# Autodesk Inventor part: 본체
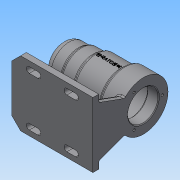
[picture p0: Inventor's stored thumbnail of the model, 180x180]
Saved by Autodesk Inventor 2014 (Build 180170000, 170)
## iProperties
Created: 2017-09
Part Number: 본체
Material: 일반
Document SubType Name: Modeling
Designer: NET
Density: 1 g/cm^3
Appearance: 기본값
Author: NET
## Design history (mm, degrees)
sketch "스케치1"
  geometry: L1 (0, 0)-(112, 0); L2 (0, 0)-(0, 25); L3 (0, 25)-(25, 25); L4 (25, 25)-(25, 27); L5 (25, 27)-(45, 27); L6 (45, 27)-(45, 30); L7 (45, 30)-(84, 30); L8 (84, 30)-(84, 34); L9 (84, 34)-(112, 34); L10 (112, 34)-(112, 0)
  constraints: 20 end point, 6 parallel, 3 perpendicular, 1 horizontal
  dimensions: "d0" = 50 diameter of L3 L1; "d1" = 54 diameter of L5 L1; "d2" = 60 diameter of L7 L1; "d3" = 68 diameter of L9 L1; "d4" = 25 distance of L2.end L3.end; "d5" = 45 distance from line of L2 L6.end; "d6" = 84 distance between parallel lines of L2 L8; "d7" = 112 distance from line of L2 L9.end
revolve "회전1" sketch "스케치1" stored, may be unused: angle "d8" = 90 deg
fillet "모깎기1" dims "d9" = 9
fillet "모깎기2" dims "d10" = 3
sketch "스케치2"
  geometry: L1 (81, -30)-(47.196, -30) reference; L2 (42, -27)-(26.644, -27) reference; L3 (22.172, -25)-(9, -25) reference; L4 (0, -16)-(0, 16) reference; L5 (9, 25)-(22.172, 25) reference; L6 (26.644, 27)-(42, 27) reference; L7 (47.196, 30)-(81, 30) reference; L8 (86.657, 34)-(112, 34) reference; L9 (112, 34)-(112, -34) reference; L10 (112, -34)-(86.657, -34) reference; L11 (6, 0)-(112, 0); L12 (112, -34)-(112, 34) reference; L13 (6, 0)-(6, 10.5); L14 (6, 10.5)-(9, 10.5); L15 (9, 10.5)-(9, 16); L16 (9, 16)-(13, 16); L17 (13, 16)-(13, 17.5); L18 (13, 17.5)-(31, 17.5); L19 (31, 17.5)-(31, 21); L20 (31, 21)-(43, 21); L21 (43, 21)-(43, 24); L22 (43, 24)-(97, 24); L23 (97, 24)-(97, 21); L24 (97, 21)-(112, 21); L25 (112, 21)-(112, 0); A1 r 3 centre (86.657, -31) between (83.828, -32) and (86.657, -34) reference; A2 r 3 centre (81, -33) between (83.828, -32) and (81, -30) reference; A3 r 3 centre (47.196, -27) between (44.598, -28.5) and (47.196, -30) reference; A4 r 3 centre (42, -30) between (44.598, -28.5) and (42, -27) reference; A5 r 3 centre (26.644, -24) between (24.408, -26) and (26.644, -27) reference; A6 r 3 centre (22.172, -28) between (24.408, -26) and (22.172, -25) reference; A7 r 9 centre (9, -16) between (0, -16) and (9, -25) reference; A8 r 9 centre (9, 16) between (9, 25) and (0, 16) reference; A9 r 3 centre (22.172, 28) between (22.172, 25) and (24.408, 26) reference; A10 r 3 centre (26.644, 24) between (26.644, 27) and (24.408, 26) reference; A11 r 3 centre (42, 30) between (42, 27) and (44.598, 28.5) reference; A12 r 3 centre (47.196, 27) between (47.196, 30) and (44.598, 28.5) reference; A13 r 3 centre (81, 33) between (81, 30) and (83.828, 32) reference; A14 r 3 centre (86.657, 31) between (86.657, 34) and (83.828, 32) reference; 1 further point
  constraints: 28 end point, 6 parallel, 6 perpendicular, 1 midpoint, 1 point on line, 1 vertical
  dimensions: "d11" = 3 distance of L13.end L14.end; "d12" = 4 distance of L15.end L16.end; "d13" = 18 distance of L17.end L18.end; "d14" = 12 distance of L19.end L20.end; "d15" = 54 distance of L21.end L22.end; "d16" = 15 distance of L23.end L24.end; "d17" = 21 diameter of L14 L11; "d18" = 32 diameter of L16 L11; "d19" = 35 diameter of L18 L11; "d20" = 42 diameter of L20 L11; "d21" = 48 diameter of L22 L11; "d22" = 42 diameter of L24 L11
revolve "회전2" sketch "스케치2" stored, may be unused: angle "d23" = 90 deg
chamfer "모따기1" distance "d24" = 1; stored, may be unused: second distance "d25" = 2, angle "d26" = 45 deg
fillet "모깎기3" dims "d27" = 3
fillet "모깎기4" dims "d28" = 0.3
fillet "모깎기5" dims "d29" = 3
sketch "스케치3" dims "d30" = 52
  geometry: C1 r 34 at (0, 0) reference; C2 r 22 at (0, 0) reference; 2 further points
  constraints: 2 vertical alignment, 1 coincident, 2 other
hole "구멍1" sketch "스케치3" at (0, 26) diameter "d31" = 3.242; stored, may be unused: countersink angle "d35" = 90 deg, drill point angle "d37" = 118 deg; dims "d32" = 8, "d33" = 4, "d34" = 2, "d36" = 11
node "작업 평면1"
sketch "스케치4"
  geometry: L1 (0, 16)-(0, -16) reference; L2 (-112, 34)-(-112, -34) reference; L3 (-86.657, 34)-(-112, 34) reference; L4 (-86.657, -34)-(-112, -34) reference; L5 (-112, 0)-(0, 0); L6 (-112, 45)-(0, 45); L7 (0, 45)-(0, -45); L8 (0, -45)-(-112, -45); L9 (-112, -45)-(-112, 45); L10 (-112, 45)-(0, -45); L11 (0, 45)-(-112, -45); 3 further points
  constraints: 14 end point, 5 midpoint, 3 parallel, 1 coincident, 1 horizontal, 1 horizontal alignment, 1 perpendicular
  dimensions: "d43" = 90 distance of L8.end L6.start; "d44" = 112 distance of L6.start L6.end
extrude "돌출1" join sketch "스케치4" distance "d45" = 8; taper "d46" = 0 deg
sketch "스케치5" dims "d43" = 90
  geometry: L1 (0, -45)-(112, -45) reference; L2 (0, 45)-(0, -45) reference; L3 (24, 34)-(36, 34); L4 (24, 30)-(36, 30); L5 (36, 38)-(24, 38); L6 (76, 34)-(88, 34); L7 (76, 30)-(88, 30); L8 (88, 38)-(76, 38); A1 r 4 centre (24, 34) between (24, 38) and (24, 30); A2 r 4 centre (36, 34) between (36, 30) and (36, 38); A3 r 4 centre (76, 34) between (76, 38) and (76, 30); A4 r 4 centre (88, 34) between (88, 30) and (88, 38); 3 further points
  constraints: 16 end point, 8 point on circle, 8 tangent, 4 centre point, 4 parallel, 2 midpoint, 1 horizontal alignment
  dimensions: "d47" = 34 vertical distance of point (0, 0) L3.start; "d48" = 4 radius of A1; "d49" = 12 distance of L3.start L3.end; "d50" = 40 distance of L6.start L3.end; "d51" = 24 distance from line of L2 L3.start; "d52" = 12 distance of L6.start L6.end; "d53" = 4 radius of A3
extrude "돌출2" cut sketch "스케치5" distance "d54" = 8; taper "d55" = 0 deg
chamfer "모따기2" distance "d56" = 12; stored, may be unused: second distance "d57" = 2, angle "d58" = 45 deg
sketch "스케치6"
  geometry: L1 (-45, -62)-(45, -62) reference; L2 (-63, -70)-(63, -70) reference; L3 (-45, -70)-(-45, -62) reference; L4 (45, -70)-(45, -62) reference; L5 (35, -62)-(21.9, -26.008); L6 (-35, -62)-(-21.9, -26.008); L7 (-35, -62)-(35, -62); L8 (30, -62)-(38, -62) reference; A1 r 34 centre (0, 0) between (21.9, -26.008) and (-21.9, -26.008) reference; 1 further point
  constraints: 6 end point, 2 point on circle, 2 point on line, 1 collinear, 2 other
  dimensions: "d59" = 10 distance from line of L3 L6.start; "d60" = 10 distance from line of L4 L5.start; "d61" = 70 deg angle of L1 L6; "d62" = 70 deg angle of L1 L5
extrude "돌출3" join sketch "스케치6" distance "d63" = 8; taper "d64" = 0 deg
sketch "스케치7"
  geometry: L1 (112, 22)-(111, 21) reference; L2 (111, 21)-(97, 21) reference; L3 (94, 24)-(46, 24) reference; L4 (43, 21)-(31.3, 21) reference; L5 (31, 20.7)-(31, 17.5) reference; L6 (31, 17.5)-(13.3, 17.5) reference; L7 (13, 17.2)-(13, 16) reference; L8 (13, 16)-(9.3, 16) reference; L9 (9, 15.7)-(9, 10.5) reference; L10 (6, 7.5)-(6, -7.5) reference; L11 (9, -10.5)-(9, -15.7) reference; L12 (9.3, -16)-(13, -16) reference; L13 (13, -16)-(13, -17.2) reference; L14 (13.3, -17.5)-(31, -17.5) reference; L15 (31, -17.5)-(31, -20.7) reference; L16 (31.3, -21)-(43, -21) reference; L17 (46, -24)-(94, -24) reference; L18 (97, -21)-(111, -21) reference; L19 (111, -21)-(112, -22) reference; L20 (112, -22)-(112, -70) reference; L21 (112, -70)-(0, -70) reference; L22 (0, -70)-(0, -62) reference; L23 (0, -62)-(104, -62) reference; L24 (104, -62)-(104, -34) reference; L25 (104, -34)-(86.657, -34) reference; L26 (81, -30)-(47.196, -30) reference; L27 (42, -27)-(26.644, -27) reference; L28 (22.172, -25)-(9, -25) reference; L29 (0, -16)-(0, 16) reference; L30 (9, 25)-(22.172, 25) reference; L31 (26.644, 27)-(42, 27) reference; L32 (47.196, 30)-(81, 30) reference; L33 (86.657, 34)-(112, 34) reference; L34 (112, 34)-(112, 27.621) reference; L35 (112, 27.621)-(101, 27.621) reference; L36 (101, 27.621)-(100.026, 26) reference; L37 (100.026, 26)-(101, 24.379) reference; L38 (101, 24.379)-(112, 24.379) reference; L39 (112, 24.379)-(112, 22) reference; L40 (112, -62)-(12, -62) reference; L41 (22, -62)-(31.378, -27); L42 (22, -62)-(104, -62); L43 (104, -62)-(112, -62) reference; L44 (104, -62)-(104, -59.048); L45 (31.378, -27)-(33.181, -24); L46 (33.181, -24)-(53.836, -28); L47 (53.836, -28)-(73.946, -28); L48 (73.946, -28)-(94, -28.5); L49 (94, -28.5)-(104, -30.437); L50 (104, -26.008)-(104, -62) reference; L51 (104, -30.437)-(104, -34); A1 r 3 centre (94, 21) between (97, 21) and (94, 24) reference; A2 r 3 centre (46, 21) between (46, 24) and (43, 21) reference; A3 r 0.3 centre (31.3, 20.7) between (31.3, 21) and (31, 20.7) reference; A4 r 0.3 centre (13.3, 17.2) between (13.3, 17.5) and (13, 17.2) reference; A5 r 0.3 centre (9.3, 15.7) between (9.3, 16) and (9, 15.7) reference; A6 r 3 centre (9, 7.5) between (9, 10.5) and (6, 7.5) reference; A7 r 3 centre (9, -7.5) between (6, -7.5) and (9, -10.5) reference; A8 r 0.3 centre (9.3, -15.7) between (9, -15.7) and (9.3, -16) reference; A9 r 0.3 centre (13.3, -17.2) between (13, -17.2) and (13.3, -17.5) reference; A10 r 0.3 centre (31.3, -20.7) between (31, -20.7) and (31.3, -21) reference; A11 r 3 centre (46, -21) between (43, -21) and (46, -24) reference; A12 r 3 centre (94, -21) between (94, -24) and (97, -21) reference; A13 r 3 centre (86.657, -31) between (83.828, -32) and (86.657, -34) reference; A14 r 3 centre (81, -33) between (83.828, -32) and (81, -30) reference; A15 r 3 centre (47.196, -27) between (44.598, -28.5) and (47.196, -30) reference; A16 r 3 centre (42, -30) between (44.598, -28.5) and (42, -27) reference; A17 r 3 centre (26.644, -24) between (24.408, -26) and (26.644, -27) reference; A18 r 3 centre (22.172, -28) between (24.408, -26) and (22.172, -25) reference; A19 r 9 centre (9, -16) between (0, -16) and (9, -25) reference; A20 r 9 centre (9, 16) between (9, 25) and (0, 16) reference; A21 r 3 centre (22.172, 28) between (22.172, 25) and (24.408, 26) reference; A22 r 3 centre (26.644, 24) between (26.644, 27) and (24.408, 26) reference; A23 r 3 centre (42, 30) between (42, 27) and (44.598, 28.5) reference; A24 r 3 centre (47.196, 27) between (47.196, 30) and (44.598, 28.5) reference; A25 r 3 centre (81, 33) between (81, 30) and (83.828, 32) reference; A26 r 3 centre (86.657, 31) between (86.657, 34) and (83.828, 32) reference; 1 further point
  constraints: 18 end point, 4 point on line, 2 collinear, 2 parallel, 1 perpendicular
  dimensions: "d65" = 105 deg angle of L23 L41; "d66" = 22 distance from line of L22 L41.start
extrude "돌출4" join sketch "스케치7" stored distance "d67" = 8; taper "d68" = 0 deg
node "작업 평면2"
sketch "스케치8"
  geometry: 5 further points; 1 other entity
  constraints: 1 horizontal alignment, 2 other
  dimensions: "d72" = 48 dimension on point (64, 0)
feature "엠보싱1" sketch "스케치8" dims "d0" = 50, "d1" = 54, "d2" = 60, "d3" = 68, "d4" = 25, "d5" = 45, "d6" = 84, "d7" = 112, "d73" = 0.5, "d74" = 0
fillet "모깎기8" dims "d75" = 3
fillet "모깎기9" dims "d76" = 3
node "솔리드1"
pattern_circular "원형 패턴1" dims angle "d39" = 360 deg
mirror "대칭1"
node "절단 모서리 투영1"
node "절단 모서리 투영2"
